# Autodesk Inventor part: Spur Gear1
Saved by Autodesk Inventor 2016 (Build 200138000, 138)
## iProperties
Created: 2015-03
Part Number: Spur Gear1
Material: Steel
Document SubType Name: Modeling
Designer: Uglješa
Categories: <?xml version="1.0" encoding="UTF-16"?> <MemberInstance><Categories><FamilyTemplate><FamilyTemplateParameter ValueType="xs:double" Id="1" ObjectReferenceKey="da
Density: 1 g/cm^3
Appearance: Steel
CustomPartVersion: 1
Author: Uglješa
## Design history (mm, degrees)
sketch "Sketch1"
  geometry: C1 r 56.77 at (0, 0)
  constraints: 1 centre point
  dimensions: "d0" = 113.5407 diameter of C1 (= da_da)
extrude "Extrusion1" new body sketch "Sketch1" distance "d1" = 20 (= da_b); taper "d2" = 0 deg
workplane "Work Plane2"
sketch "Sketch2"
  geometry: C1 r 56.77 at (0, 0) reference; C2 r 54.857 at (0, 0)
  constraints: 1 centre point, 1 coincident
  dimensions: "d3" = 109.71429 diameter of C2 (= da_dw)
feature "Pitch Diameter" sketch "Sketch2" dims "d4" = 10, "d5" = 0
workplane "Work Plane8"
workplane "Work Plane9"
feature "Spur Gear" dims "da_b" = 20, "da_d" = 109.06138, "da_aw" = 80, "da_da" = 113.5407, "da_df" = 103.43638, "da_dw" = 109.71429, angle "da_beta" = 8 deg, "da_lefttooth" = 10, "da_righttooth" = 0
node "Keyway3"
body "Solid1"
body "Srf1"
feature "Hub Keyway"
other parameters: "d17" = 0, "d34" = 0.6545 (computed from da_z), "d39" = 0, "d41" = 0, "d47" = 0, "d48" = 0
